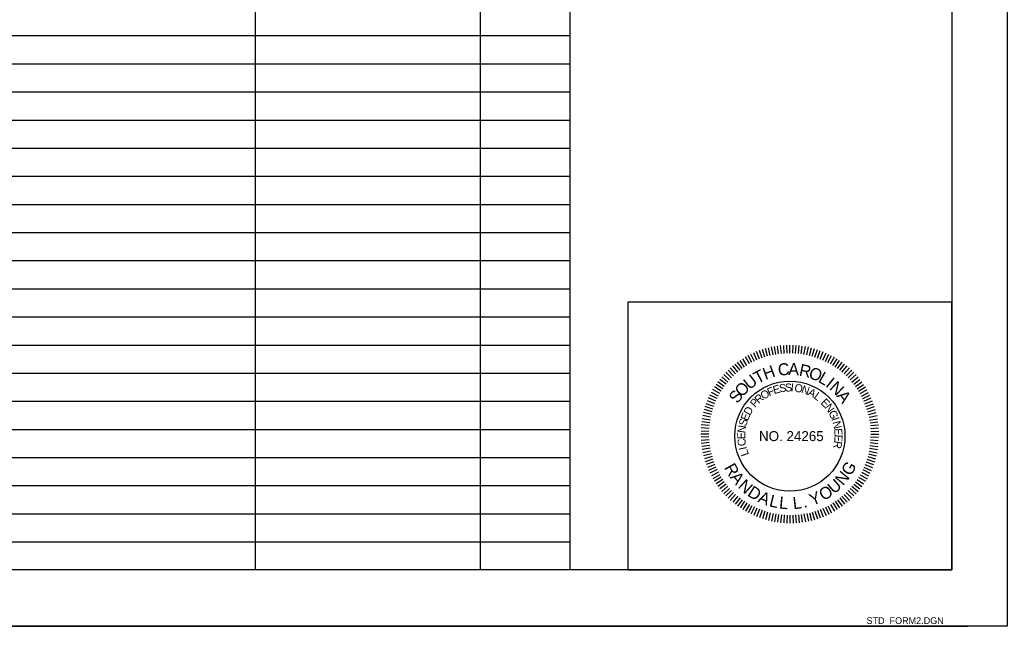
# Model space of a CAD drawing. Extents: x 8134 to 11793, y 3225 to 13425.
# Drawn here: x 11338.3 to 11777.4, y 7750 to 8019.6 of the extents above; entities that cross this region are included whole.
import ezdxf

# ---------------------------------------------------------------- set-up
doc = ezdxf.new("R2010")
doc.units = 0
for name, color, linetype in [('RD_SHT_Bndy', 7, 'Continuous'), ('RD_SHT_IplotShp', 7, 'Continuous'), ('RD_SHT_TX', 7, 'Continuous'), ('RD_TX_PEShield', 7, 'Continuous')]:
    doc.layers.add(name, color=color, linetype=linetype)

msp = doc.modelspace()

# ---------------------------------------------------------------- linework, layer by layer
at = {"layer": 'RD_SHT_Bndy'}
for p, q in [((11442.95, 8750), (11442.95, 7775)), ((11542.95, 8750), (11542.95, 7775)), ((11582.95, 8750), (11582.95, 7775)), ((10932.95, 8012.5), (11582.95, 8012.5)), ((10932.95, 8000), (11582.95, 8000)), ((10932.95, 7987.5), (11582.95, 7987.5)), ((10932.95, 7975), (11582.95, 7975)), ((10932.95, 7962.5), (11582.95, 7962.5)), ((10932.95, 7950), (11582.95, 7950)), ((10932.95, 7937.5), (11582.95, 7937.5)), ((10932.95, 7925), (11582.95, 7925)), ((10932.95, 7912.5), (11582.95, 7912.5)), ((10932.95, 7900), (11582.95, 7900)), ((10932.95, 7887.5), (11582.95, 7887.5)), ((10932.95, 7875), (11582.95, 7875)), ((10932.95, 7862.5), (11582.95, 7862.5)), ((10932.95, 7850), (11582.95, 7850)), ((10932.95, 7837.5), (11582.95, 7837.5)), ((10932.95, 7825), (11582.95, 7825)), ((10932.95, 7812.5), (11582.95, 7812.5)), ((10932.95, 7800), (11582.95, 7800)), ((10932.95, 7787.5), (11582.95, 7787.5)), ((10000, 7750), (11760, 7750)), ((11760, 7750), (10000, 7750))]:
    msp.add_line(p, q, dxfattribs=at)
for points in [[(10077.75, 8825), (11752.75, 8825), (11752.75, 7775), (10077.75, 7775)], [(11608.75, 7775), (11752.75, 7775), (11752.75, 7894), (11608.75, 7894)]]:
    msp.add_lwpolyline(points, close=True, dxfattribs=at)
at = {"layer": 'RD_SHT_IplotShp'}
msp.add_lwpolyline([(9981.41, 8850), (11777.4, 8850), (11777.4, 7750), (9981.41, 7750)], close=True, dxfattribs=at)
at = {"layer": 'RD_TX_PEShield'}
for p, q in [((11672.04, 7870.31), (11671.18, 7873.76)), ((11672.04, 7870.31), (11671.18, 7873.76)), ((11673.26, 7870.64), (11672.52, 7874.12)), ((11673.26, 7870.64), (11672.52, 7874.12)), ((11674.5, 7870.83), (11673.88, 7874.33)), ((11674.5, 7870.83), (11673.88, 7874.33)), ((11675.74, 7871.03), (11675.24, 7874.55)), ((11675.74, 7871.03), (11675.24, 7874.55)), ((11676.98, 7871.23), (11676.61, 7874.77)), ((11676.98, 7871.23), (11676.61, 7874.77)), ((11678.24, 7871.29), (11677.99, 7874.84)), ((11678.24, 7871.29), (11677.99, 7874.84)), ((11679.49, 7871.36), (11679.37, 7874.91)), ((11679.49, 7871.36), (11679.37, 7874.91)), ((11680.75, 7871.42), (11680.75, 7874.98)), ((11680.75, 7871.42), (11680.75, 7874.98)), ((11682.01, 7871.36), (11682.13, 7874.91)), ((11682.01, 7871.36), (11682.13, 7874.91)), ((11683.26, 7871.29), (11683.51, 7874.84)), ((11683.26, 7871.29), (11683.51, 7874.84)), ((11684.52, 7871.23), (11684.89, 7874.77)), ((11684.52, 7871.23), (11684.89, 7874.77)), ((11685.76, 7871.03), (11686.26, 7874.55)), ((11685.76, 7871.03), (11686.26, 7874.55)), ((11687, 7870.83), (11687.62, 7874.33)), ((11687, 7870.83), (11687.62, 7874.33)), ((11688.24, 7870.64), (11688.98, 7874.12)), ((11688.24, 7870.64), (11688.98, 7874.12)), ((11688.24, 7870.64), (11688.98, 7874.12)), ((11689.46, 7870.31), (11690.32, 7873.76)), ((11689.46, 7870.31), (11690.32, 7873.76)), ((11689.46, 7870.31), (11690.32, 7873.76)), ((11662.73, 7866.59), (11660.95, 7869.68)), ((11662.73, 7866.59), (11660.95, 7869.68)), ((11663.85, 7867.17), (11662.18, 7870.3)), ((11663.85, 7867.17), (11662.18, 7870.3)), ((11664.97, 7867.74), (11663.41, 7870.93)), ((11664.97, 7867.74), (11663.41, 7870.93)), ((11666.09, 7868.31), (11664.64, 7871.56)), ((11666.09, 7868.31), (11664.64, 7871.56)), ((11667.26, 7868.76), (11665.93, 7872.05)), ((11667.26, 7868.76), (11665.93, 7872.05)), ((11668.44, 7869.21), (11667.22, 7872.55)), ((11668.44, 7869.21), (11667.22, 7872.55)), ((11669.61, 7869.66), (11668.51, 7873.04)), ((11669.61, 7869.66), (11668.51, 7873.04)), ((11670.83, 7869.98), (11669.85, 7873.4)), ((11670.83, 7869.98), (11669.85, 7873.4)), ((11690.67, 7869.98), (11691.65, 7873.4)), ((11690.67, 7869.98), (11691.65, 7873.4)), ((11690.67, 7869.98), (11691.65, 7873.4)), ((11691.89, 7869.66), (11692.99, 7873.04)), ((11691.89, 7869.66), (11692.99, 7873.04)), ((11691.89, 7869.66), (11692.99, 7873.04)), ((11693.06, 7869.21), (11694.28, 7872.55)), ((11693.06, 7869.21), (11694.28, 7872.55)), ((11693.06, 7869.21), (11694.28, 7872.55)), ((11694.24, 7868.76), (11695.57, 7872.05)), ((11694.24, 7868.76), (11695.57, 7872.05)), ((11694.24, 7868.76), (11695.57, 7872.05)), ((11695.41, 7868.31), (11696.86, 7871.56)), ((11695.41, 7868.31), (11696.86, 7871.56)), ((11695.41, 7868.31), (11696.86, 7871.56)), ((11696.53, 7867.74), (11698.09, 7870.93)), ((11696.53, 7867.74), (11698.09, 7870.93)), ((11696.53, 7867.74), (11698.09, 7870.93)), ((11697.65, 7867.17), (11699.32, 7870.3)), ((11697.65, 7867.17), (11699.32, 7870.3)), ((11697.65, 7867.17), (11699.32, 7870.3)), ((11698.77, 7866.59), (11700.55, 7869.68)), ((11698.77, 7866.59), (11700.55, 7869.68)), ((11698.77, 7866.59), (11700.55, 7869.68)), ((11656.63, 7862.16), (11654.25, 7864.81)), ((11656.63, 7862.16), (11654.25, 7864.81)), ((11657.61, 7862.96), (11655.32, 7865.68)), ((11657.61, 7862.96), (11655.32, 7865.68)), ((11658.59, 7863.75), (11656.4, 7866.55)), ((11658.59, 7863.75), (11656.4, 7866.55)), ((11659.56, 7864.54), (11657.47, 7867.42)), ((11659.56, 7864.54), (11657.47, 7867.42)), ((11660.62, 7865.22), (11658.63, 7868.17)), ((11660.62, 7865.22), (11658.63, 7868.17)), ((11661.67, 7865.91), (11659.79, 7868.92)), ((11661.67, 7865.91), (11659.79, 7868.92)), ((11699.83, 7865.91), (11701.71, 7868.92)), ((11699.83, 7865.91), (11701.71, 7868.92)), ((11699.83, 7865.91), (11701.71, 7868.92)), ((11700.88, 7865.22), (11702.87, 7868.17)), ((11700.88, 7865.22), (11702.87, 7868.17)), ((11700.88, 7865.22), (11702.87, 7868.17)), ((11701.94, 7864.54), (11704.03, 7867.42)), ((11701.94, 7864.54), (11704.03, 7867.42)), ((11701.94, 7864.54), (11704.03, 7867.42)), ((11702.91, 7863.75), (11705.1, 7866.55)), ((11702.91, 7863.75), (11705.1, 7866.55)), ((11702.91, 7863.75), (11705.1, 7866.55)), ((11703.89, 7862.96), (11706.18, 7865.68)), ((11703.89, 7862.96), (11706.18, 7865.68)), ((11703.89, 7862.96), (11706.18, 7865.68)), ((11704.87, 7862.16), (11707.25, 7864.81)), ((11704.87, 7862.16), (11707.25, 7864.81)), ((11704.87, 7862.16), (11707.25, 7864.81)), ((11653.17, 7858.52), (11650.45, 7860.8)), ((11653.17, 7858.52), (11650.45, 7860.8)), ((11653.96, 7859.5), (11651.32, 7861.88)), ((11653.96, 7859.5), (11651.32, 7861.88)), ((11654.85, 7860.39), (11652.3, 7862.86)), ((11654.85, 7860.39), (11652.3, 7862.86)), ((11655.74, 7861.28), (11653.27, 7863.83)), ((11655.74, 7861.28), (11653.27, 7863.83)), ((11705.76, 7861.28), (11708.23, 7863.83)), ((11705.76, 7861.28), (11708.23, 7863.83)), ((11705.76, 7861.28), (11708.23, 7863.83)), ((11706.65, 7860.39), (11709.2, 7862.86)), ((11706.65, 7860.39), (11709.2, 7862.86)), ((11706.65, 7860.39), (11709.2, 7862.86)), ((11707.54, 7859.5), (11710.18, 7861.88)), ((11707.54, 7859.5), (11710.18, 7861.88)), ((11707.54, 7859.5), (11710.18, 7861.88)), ((11708.33, 7858.52), (11711.05, 7860.8)), ((11708.33, 7858.52), (11711.05, 7860.8)), ((11708.33, 7858.52), (11711.05, 7860.8)), ((11650.22, 7854.46), (11647.2, 7856.34)), ((11650.22, 7854.46), (11647.2, 7856.34)), ((11650.9, 7855.51), (11647.96, 7857.5)), ((11650.9, 7855.51), (11647.96, 7857.5)), ((11651.59, 7856.56), (11648.71, 7858.66)), ((11651.59, 7856.56), (11648.71, 7858.66)), ((11652.38, 7857.54), (11649.58, 7859.73)), ((11652.38, 7857.54), (11649.58, 7859.73)), ((11709.12, 7857.54), (11711.92, 7859.73)), ((11709.12, 7857.54), (11711.92, 7859.73)), ((11709.12, 7857.54), (11711.92, 7859.73)), ((11709.91, 7856.56), (11712.79, 7858.66)), ((11709.91, 7856.56), (11712.79, 7858.66)), ((11709.91, 7856.56), (11712.79, 7858.66)), ((11710.6, 7855.51), (11713.54, 7857.5)), ((11710.6, 7855.51), (11713.54, 7857.5)), ((11710.6, 7855.51), (11713.54, 7857.5)), ((11711.28, 7854.46), (11714.3, 7856.34)), ((11711.28, 7854.46), (11714.3, 7856.34)), ((11711.28, 7854.46), (11714.3, 7856.34)), ((11648.39, 7851.16), (11645.2, 7852.72)), ((11648.39, 7851.16), (11645.2, 7852.72)), ((11648.96, 7852.28), (11645.82, 7853.95)), ((11648.96, 7852.28), (11645.82, 7853.95)), ((11649.53, 7853.4), (11646.45, 7855.18)), ((11649.53, 7853.4), (11646.45, 7855.18)), ((11711.97, 7853.4), (11715.05, 7855.18)), ((11711.97, 7853.4), (11715.05, 7855.18)), ((11711.97, 7853.4), (11715.05, 7855.18)), ((11712.54, 7852.28), (11715.68, 7853.95)), ((11712.54, 7852.28), (11715.68, 7853.95)), ((11712.54, 7852.28), (11715.68, 7853.95)), ((11713.11, 7851.16), (11716.3, 7852.72)), ((11713.11, 7851.16), (11716.3, 7852.72)), ((11713.11, 7851.16), (11716.3, 7852.72)), ((11646.47, 7846.52), (11643.08, 7847.62)), ((11646.47, 7846.52), (11643.08, 7847.62)), ((11646.92, 7847.69), (11643.58, 7848.91)), ((11646.92, 7847.69), (11643.58, 7848.91)), ((11647.37, 7848.86), (11644.07, 7850.2)), ((11647.37, 7848.86), (11644.07, 7850.2)), ((11647.82, 7850.04), (11644.57, 7851.49)), ((11647.82, 7850.04), (11644.57, 7851.49)), ((11713.68, 7850.04), (11716.93, 7851.49)), ((11713.68, 7850.04), (11716.93, 7851.49)), ((11713.68, 7850.04), (11716.93, 7851.49)), ((11714.13, 7848.86), (11717.43, 7850.2)), ((11714.13, 7848.86), (11717.43, 7850.2)), ((11714.13, 7848.86), (11717.43, 7850.2)), ((11714.58, 7847.69), (11717.92, 7848.91)), ((11714.58, 7847.69), (11717.92, 7848.91)), ((11714.58, 7847.69), (11717.92, 7848.91)), ((11715.03, 7846.52), (11718.42, 7847.62)), ((11715.03, 7846.52), (11718.42, 7847.62)), ((11715.03, 7846.52), (11718.42, 7847.62)), ((11645.49, 7842.87), (11642.01, 7843.61)), ((11645.49, 7842.87), (11642.01, 7843.61)), ((11645.82, 7844.09), (11642.37, 7844.95)), ((11645.82, 7844.09), (11642.37, 7844.95)), ((11646.14, 7845.3), (11642.73, 7846.28)), ((11646.14, 7845.3), (11642.73, 7846.28)), ((11715.36, 7845.3), (11718.77, 7846.28)), ((11715.36, 7845.3), (11718.77, 7846.28)), ((11715.36, 7845.3), (11718.77, 7846.28)), ((11715.68, 7844.09), (11719.13, 7844.95)), ((11715.68, 7844.09), (11719.13, 7844.95)), ((11715.68, 7844.09), (11719.13, 7844.95)), ((11716.01, 7842.87), (11719.49, 7843.61)), ((11716.01, 7842.87), (11719.49, 7843.61)), ((11716.01, 7842.87), (11719.49, 7843.61)), ((11644.9, 7839.15), (11641.36, 7839.52)), ((11644.9, 7839.15), (11641.36, 7839.52)), ((11645.1, 7840.39), (11641.58, 7840.88)), ((11645.1, 7840.39), (11641.58, 7840.88)), ((11645.3, 7841.63), (11641.79, 7842.25)), ((11645.3, 7841.63), (11641.79, 7842.25)), ((11716.2, 7841.63), (11719.71, 7842.25)), ((11716.2, 7841.63), (11719.71, 7842.25)), ((11716.2, 7841.63), (11719.71, 7842.25)), ((11716.4, 7840.39), (11719.92, 7840.88)), ((11716.4, 7840.39), (11719.92, 7840.88)), ((11716.4, 7840.39), (11719.92, 7840.88)), ((11716.6, 7839.15), (11720.14, 7839.52)), ((11716.6, 7839.15), (11720.14, 7839.52)), ((11716.6, 7839.15), (11720.14, 7839.52)), ((11644.71, 7835.38), (11641.15, 7835.38)), ((11644.71, 7835.38), (11641.15, 7835.38)), ((11644.77, 7836.63), (11641.22, 7836.76)), ((11644.77, 7836.63), (11641.22, 7836.76)), ((11644.77, 7834.12), (11641.22, 7834)), ((11644.77, 7834.12), (11641.22, 7834)), ((11644.84, 7837.89), (11641.29, 7838.14)), ((11644.84, 7837.89), (11641.29, 7838.14)), ((11716.66, 7837.89), (11720.21, 7838.14)), ((11716.66, 7837.89), (11720.21, 7838.14)), ((11716.66, 7837.89), (11720.21, 7838.14)), ((11716.66, 7834.12), (11720.21, 7834)), ((11716.66, 7834.12), (11720.21, 7834)), ((11716.73, 7836.63), (11720.28, 7836.76)), ((11716.73, 7836.63), (11720.28, 7836.76)), ((11716.73, 7836.63), (11720.28, 7836.76)), ((11716.8, 7835.38), (11720.36, 7835.38)), ((11716.8, 7835.38), (11720.36, 7835.38)), ((11716.8, 7835.38), (11720.36, 7835.38)), ((11644.84, 7832.87), (11641.29, 7832.62)), ((11644.84, 7832.87), (11641.29, 7832.62)), ((11644.9, 7831.61), (11641.36, 7831.24)), ((11644.9, 7831.61), (11641.36, 7831.24)), ((11645.1, 7830.37), (11641.58, 7829.87)), ((11645.1, 7830.37), (11641.58, 7829.87)), ((11716.27, 7830.39), (11719.78, 7829.89)), ((11716.27, 7830.39), (11719.78, 7829.89)), ((11716.4, 7831.63), (11719.92, 7831.26)), ((11716.4, 7831.63), (11719.92, 7831.26)), ((11716.53, 7832.88), (11720.07, 7832.63)), ((11716.53, 7832.88), (11720.07, 7832.63)), ((11645.3, 7829.13), (11641.79, 7828.51)), ((11645.3, 7829.13), (11641.79, 7828.51)), ((11645.49, 7827.88), (11642.01, 7827.14)), ((11645.49, 7827.88), (11642.01, 7827.14)), ((11645.82, 7826.67), (11642.37, 7825.81)), ((11645.82, 7826.67), (11642.37, 7825.81)), ((11646.14, 7825.45), (11642.73, 7824.47)), ((11646.14, 7825.45), (11642.73, 7824.47)), ((11715.36, 7825.45), (11718.77, 7824.47)), ((11715.36, 7825.45), (11718.77, 7824.47)), ((11715.68, 7826.67), (11719.13, 7825.81)), ((11715.68, 7826.67), (11719.13, 7825.81)), ((11716.01, 7827.88), (11719.49, 7827.14)), ((11716.01, 7827.88), (11719.49, 7827.14)), ((11716.14, 7829.14), (11719.63, 7828.52)), ((11716.14, 7829.14), (11719.63, 7828.52)), ((11646.47, 7824.24), (11643.08, 7823.14)), ((11646.92, 7823.06), (11643.58, 7821.85)), ((11646.92, 7823.06), (11643.58, 7821.85)), ((11647.37, 7821.89), (11644.07, 7820.56)), ((11647.37, 7821.89), (11644.07, 7820.56)), ((11714.13, 7821.89), (11717.43, 7820.56)), ((11714.13, 7821.89), (11717.43, 7820.56)), ((11714.58, 7823.06), (11717.92, 7821.85)), ((11714.58, 7823.06), (11717.92, 7821.85)), ((11715.03, 7824.24), (11718.42, 7823.14)), ((11715.03, 7824.24), (11718.42, 7823.14)), ((11647.82, 7820.72), (11644.57, 7819.27)), ((11647.82, 7820.72), (11644.57, 7819.27)), ((11648.39, 7819.6), (11645.2, 7818.04)), ((11648.39, 7819.6), (11645.2, 7818.04)), ((11648.96, 7818.48), (11645.82, 7816.81)), ((11648.96, 7818.48), (11645.82, 7816.81)), ((11649.53, 7817.36), (11646.45, 7815.58)), ((11649.53, 7817.36), (11646.45, 7815.58)), ((11711.97, 7817.36), (11715.05, 7815.58)), ((11711.97, 7817.36), (11715.05, 7815.58)), ((11712.54, 7818.48), (11715.68, 7816.81)), ((11712.54, 7818.48), (11715.68, 7816.81)), ((11713.11, 7819.6), (11716.3, 7818.04)), ((11713.11, 7819.6), (11716.3, 7818.04)), ((11713.68, 7820.72), (11716.93, 7819.27)), ((11713.68, 7820.72), (11716.93, 7819.27)), ((11650.22, 7816.3), (11647.2, 7814.42)), ((11650.22, 7816.3), (11647.2, 7814.42)), ((11650.9, 7815.25), (11647.96, 7813.26)), ((11650.9, 7815.25), (11647.96, 7813.26)), ((11651.59, 7814.19), (11648.71, 7812.1)), ((11651.59, 7814.19), (11648.71, 7812.1)), ((11652.38, 7813.21), (11649.58, 7811.02)), ((11652.38, 7813.21), (11649.58, 7811.02)), ((11653.17, 7812.24), (11650.45, 7809.95)), ((11653.17, 7812.24), (11650.45, 7809.95)), ((11708.33, 7812.24), (11711.05, 7809.95)), ((11708.33, 7812.24), (11711.05, 7809.95)), ((11709.12, 7813.21), (11711.92, 7811.02)), ((11709.12, 7813.21), (11711.92, 7811.02)), ((11709.91, 7814.19), (11712.79, 7812.1)), ((11709.91, 7814.19), (11712.79, 7812.1)), ((11710.6, 7815.25), (11713.54, 7813.26)), ((11710.6, 7815.25), (11713.54, 7813.26)), ((11711.28, 7816.3), (11714.3, 7814.42)), ((11711.28, 7816.3), (11714.3, 7814.42)), ((11653.96, 7811.26), (11651.32, 7808.88)), ((11653.96, 7811.26), (11651.32, 7808.88)), ((11654.85, 7810.37), (11652.3, 7807.9)), ((11654.85, 7810.37), (11652.3, 7807.9)), ((11655.74, 7809.48), (11653.27, 7806.92)), ((11655.74, 7809.48), (11653.27, 7806.92)), ((11656.63, 7808.59), (11654.25, 7805.95)), ((11656.63, 7808.59), (11654.25, 7805.95)), ((11657.61, 7807.8), (11655.32, 7805.08)), ((11657.61, 7807.8), (11655.32, 7805.08)), ((11703.89, 7807.8), (11706.18, 7805.08)), ((11703.89, 7807.8), (11706.18, 7805.08)), ((11704.87, 7808.59), (11707.25, 7805.95)), ((11705.76, 7809.48), (11708.23, 7806.92)), ((11705.76, 7809.48), (11708.23, 7806.92)), ((11706.65, 7810.37), (11709.2, 7807.9)), ((11706.65, 7810.37), (11709.2, 7807.9)), ((11707.54, 7811.26), (11710.18, 7808.88)), ((11707.54, 7811.26), (11710.18, 7808.88)), ((11658.59, 7807.01), (11656.4, 7804.21)), ((11658.59, 7807.01), (11656.4, 7804.21)), ((11659.56, 7806.22), (11657.47, 7803.34)), ((11659.56, 7806.22), (11657.47, 7803.34)), ((11660.62, 7805.53), (11658.63, 7802.58)), ((11660.62, 7805.53), (11658.63, 7802.58)), ((11661.67, 7804.85), (11659.79, 7801.83)), ((11661.67, 7804.85), (11659.79, 7801.83)), ((11662.73, 7804.16), (11660.95, 7801.08)), ((11662.73, 7804.16), (11660.95, 7801.08)), ((11663.85, 7803.59), (11662.18, 7800.45)), ((11663.85, 7803.59), (11662.18, 7800.45)), ((11697.65, 7803.59), (11699.32, 7800.45)), ((11697.65, 7803.59), (11699.32, 7800.45)), ((11698.77, 7804.16), (11700.55, 7801.08)), ((11698.77, 7804.16), (11700.55, 7801.08)), ((11699.83, 7804.85), (11701.71, 7801.83)), ((11699.83, 7804.85), (11701.71, 7801.83)), ((11700.88, 7805.53), (11702.87, 7802.58)), ((11700.88, 7805.53), (11702.87, 7802.58)), ((11701.94, 7806.22), (11704.03, 7803.34)), ((11701.94, 7806.22), (11704.03, 7803.34)), ((11702.91, 7807.01), (11705.1, 7804.21)), ((11702.91, 7807.01), (11705.1, 7804.21)), ((11664.97, 7803.02), (11663.41, 7799.82)), ((11664.97, 7803.02), (11663.41, 7799.82)), ((11666.09, 7802.45), (11664.64, 7799.2)), ((11666.09, 7802.45), (11664.64, 7799.2)), ((11667.26, 7802), (11665.93, 7798.7)), ((11667.26, 7802), (11665.93, 7798.7)), ((11668.44, 7801.55), (11667.22, 7798.21)), ((11668.44, 7801.55), (11667.22, 7798.21)), ((11669.61, 7801.1), (11668.51, 7797.71)), ((11669.61, 7801.1), (11668.51, 7797.71)), ((11670.83, 7800.77), (11669.85, 7797.35)), ((11670.83, 7800.77), (11669.85, 7797.35)), ((11672.04, 7800.45), (11671.18, 7797)), ((11672.04, 7800.45), (11671.18, 7797)), ((11673.26, 7800.12), (11672.52, 7796.64)), ((11673.26, 7800.12), (11672.52, 7796.64)), ((11674.5, 7799.92), (11673.88, 7796.42)), ((11674.5, 7799.92), (11673.88, 7796.42)), ((11675.74, 7799.73), (11675.24, 7796.21)), ((11675.74, 7799.73), (11675.24, 7796.21)), ((11676.98, 7799.53), (11676.61, 7795.99)), ((11676.98, 7799.53), (11676.61, 7795.99)), ((11678.24, 7799.46), (11677.99, 7795.92)), ((11678.24, 7799.46), (11677.99, 7795.92)), ((11679.49, 7799.4), (11679.37, 7795.85)), ((11679.49, 7799.4), (11679.37, 7795.85)), ((11680.75, 7799.33), (11680.75, 7795.77)), ((11680.75, 7799.33), (11680.75, 7795.77)), ((11682.01, 7799.4), (11682.13, 7795.85)), ((11682.01, 7799.4), (11682.13, 7795.85)), ((11683.26, 7799.46), (11683.51, 7795.92)), ((11683.26, 7799.46), (11683.51, 7795.92)), ((11684.52, 7799.53), (11684.89, 7795.99)), ((11684.52, 7799.53), (11684.89, 7795.99)), ((11685.76, 7799.73), (11686.26, 7796.21)), ((11685.76, 7799.73), (11686.26, 7796.21)), ((11687, 7799.92), (11687.62, 7796.42)), ((11687, 7799.92), (11687.62, 7796.42)), ((11688.24, 7800.12), (11688.98, 7796.64)), ((11688.24, 7800.12), (11688.98, 7796.64)), ((11689.46, 7800.45), (11690.32, 7797)), ((11689.46, 7800.45), (11690.32, 7797)), ((11690.67, 7800.77), (11691.65, 7797.35)), ((11690.67, 7800.77), (11691.65, 7797.35)), ((11691.89, 7801.1), (11692.99, 7797.71)), ((11691.89, 7801.1), (11692.99, 7797.71)), ((11693.06, 7801.55), (11694.28, 7798.21)), ((11693.06, 7801.55), (11694.28, 7798.21)), ((11694.24, 7802), (11695.57, 7798.7)), ((11694.24, 7802), (11695.57, 7798.7)), ((11695.41, 7802.45), (11696.86, 7799.2)), ((11695.41, 7802.45), (11696.86, 7799.2)), ((11696.53, 7803.02), (11698.09, 7799.82)), ((11696.53, 7803.02), (11698.09, 7799.82))]:
    msp.add_line(p, q, dxfattribs=at)
msp.add_circle((11680.75, 7834.5), 24.48, dxfattribs=at)

# ---------------------------------------------------------------- texts
at = {"layer": 'RD_SHT_TX'}
msp.add_text('STD_FORM2.DGN', height=3, dxfattribs=at).set_placement((11714.82, 7750.99))
at = {"layer": 'RD_TX_PEShield'}
for s, height, rotation, p in [('H', 5.34, 19.9102, (11669.85, 7859.42)), ('C', 5.34, 6.8832, (11675.74, 7861.24)), ('A', 5.34, 357.9448, (11679.96, 7861.69)), ('R', 5.34, 348.267, (11684.54, 7861.44)), ('O', 5.34, 339.3286, (11688.68, 7860.52)), ('U', 5.34, 37.7726, (11662.73, 7854.88)), ('T', 5.34, 28.0947, (11666.41, 7857.62)), ('L', 5.34, 329.6507, (11692.94, 7858.82)), ('I', 5.34, 321.4663, (11696.28, 7856.83)), ('O', 5.34, 47.4504, (11659.56, 7851.56)), ('F', 3.56, 23.0853, (11671.56, 7852.16)), ('E', 3.56, 16.1843, (11673.75, 7853.13)), ('S', 3.56, 8.6909, (11676.24, 7853.89)), ('S', 3.56, 1.79, (11678.6, 7854.29)), ('I', 3.56, 354.889, (11680.99, 7854.4)), ('O', 3.56, 350.4045, (11682.55, 7854.32)), ('N', 3.56, 341.7029, (11685.53, 7853.82)), ('N', 5.34, 317.0007, (11697.97, 7855.56)), ('S', 5.34, 54.9027, (11657.53, 7848.66)), ('R', 3.56, 39.8902, (11666.85, 7848.75)), ('O', 3.56, 31.7869, (11668.99, 7850.56)), ('A', 3.56, 333.0013, (11688.4, 7852.88)), ('L', 3.56, 324.2997, (11691.09, 7851.51)), ('A', 5.34, 307.3229, (11701.27, 7852.36)), ('D', 3.56, 59.074, (11662.94, 7843.39)), ('P', 3.56, 46.7912, (11665.24, 7846.97)), ('E', 3.56, 313.2251, (11694.16, 7849.21)), ('N', 3.56, 305.7317, (11695.97, 7847.33)), ('E', 3.56, 66.5674, (11661.93, 7840.99)), ('G', 3.56, 297.0301, (11697.73, 7844.88)), ('I', 3.56, 288.3285, (11699.11, 7842.19)), ('N', 3.56, 82.17, (11660.88, 7835.69)), ('S', 3.56, 73.4683, (11661.29, 7838.68)), ('N', 3.56, 283.8441, (11699.65, 7840.74)), ('E', 3.56, 89.6633, (11660.89, 7833.09)), ('E', 3.56, 275.1424, (11700.38, 7837.8)), ('E', 3.56, 267.6491, (11700.64, 7835.22)), ('C', 3.56, 97.7667, (11661.29, 7830.3)), ('I', 3.56, 102.2511, (11661.68, 7828.79)), ('R', 3.56, 260.1557, (11700.57, 7832.61)), ('L', 3.56, 109.7445, (11662.59, 7826.35)), ('R', 5.34, 299.1493, (11651.35, 7820.53)), ('G', 5.34, 60.1113, (11707.86, 7816.48)), ('A', 5.34, 308.0877, (11653.88, 7816.13)), ('N', 5.34, 50.4335, (11704.44, 7812.18)), ('N', 5.34, 317.7655, (11657.35, 7811.87)), ('D', 5.34, 327.4433, (11661.48, 7808.26)), ('O', 5.34, 31.0778, (11695.71, 7805.58)), ('U', 5.34, 40.7556, (11700.35, 7808.51)), ('A', 5.34, 337.1212, (11666.17, 7805.39)), ('L', 5.34, 346.799, (11671.27, 7803.36)), ('Y', 5.34, 21.4, (11690.63, 7803.48)), ('L', 5.34, 354.9835, (11675.8, 7802.32)), ('L', 5.34, 6.5171, (11682.33, 7801.98)), ('.', 5.34, 14.7016, (11686.95, 7802.54))]:
    msp.add_text(s, height=height, rotation=rotation, dxfattribs=at).set_placement(p)
msp.add_text('NO. 24265', height=4.45, dxfattribs=at).set_placement((11667, 7832.28))

doc.saveas('drawing.dxf')
